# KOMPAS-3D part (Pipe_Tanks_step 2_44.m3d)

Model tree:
1. X Axis
2. Y Axis
3. Z Axis  (labels: Pipe Dn 50)
     Òîëùèíà ñòåíêè 1 = 1

Referenced files in C:\Documents and Settings\kashirsky\Мои документы\Camtasia Studio\Pipelines3D\Tanks\: Tanks_step 2.a3d
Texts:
  Pipe Dn 50
  Steel ASTM A295
  Three Point Plane
  Plane at Angle
  Line and Point Plane
  Axis through Two Vertices
  Axis of Feature
  Axis of Conical Surface
  Axis through Edge
  Trim by Surface
  Trim by Sketch
  Feature with No History
  Intersection Axis of Two Planes
  Two Line Plane
  Line and Face Plane
  Bend by line
  Hole in sheet body
  Cut in sheet body
  Point in CM
  Linear Dimension from Line to Point
  Surface Finish Symbol
  Geometric Tolerance Symbol
  Leader #1
  Leader #2
  Leader #3
  Shape Deviations and Datum
  Node point number
  Mark of coordination axis
  Node point designation
  Mark/Reference designation with leader
  Mark/reference designation on line
  Mark/Reference designation without leader
  Plane of section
